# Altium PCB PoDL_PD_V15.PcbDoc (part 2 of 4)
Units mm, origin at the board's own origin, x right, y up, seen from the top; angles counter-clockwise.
Board outline 145 x 75 mm, 4 copper layers (Top Layer, Signal Layer 2, Signal Layer 3, Bottom Layer), stack 1.586 mm thick; 346 components, 228 nets, 1035 pads, 619 vias.
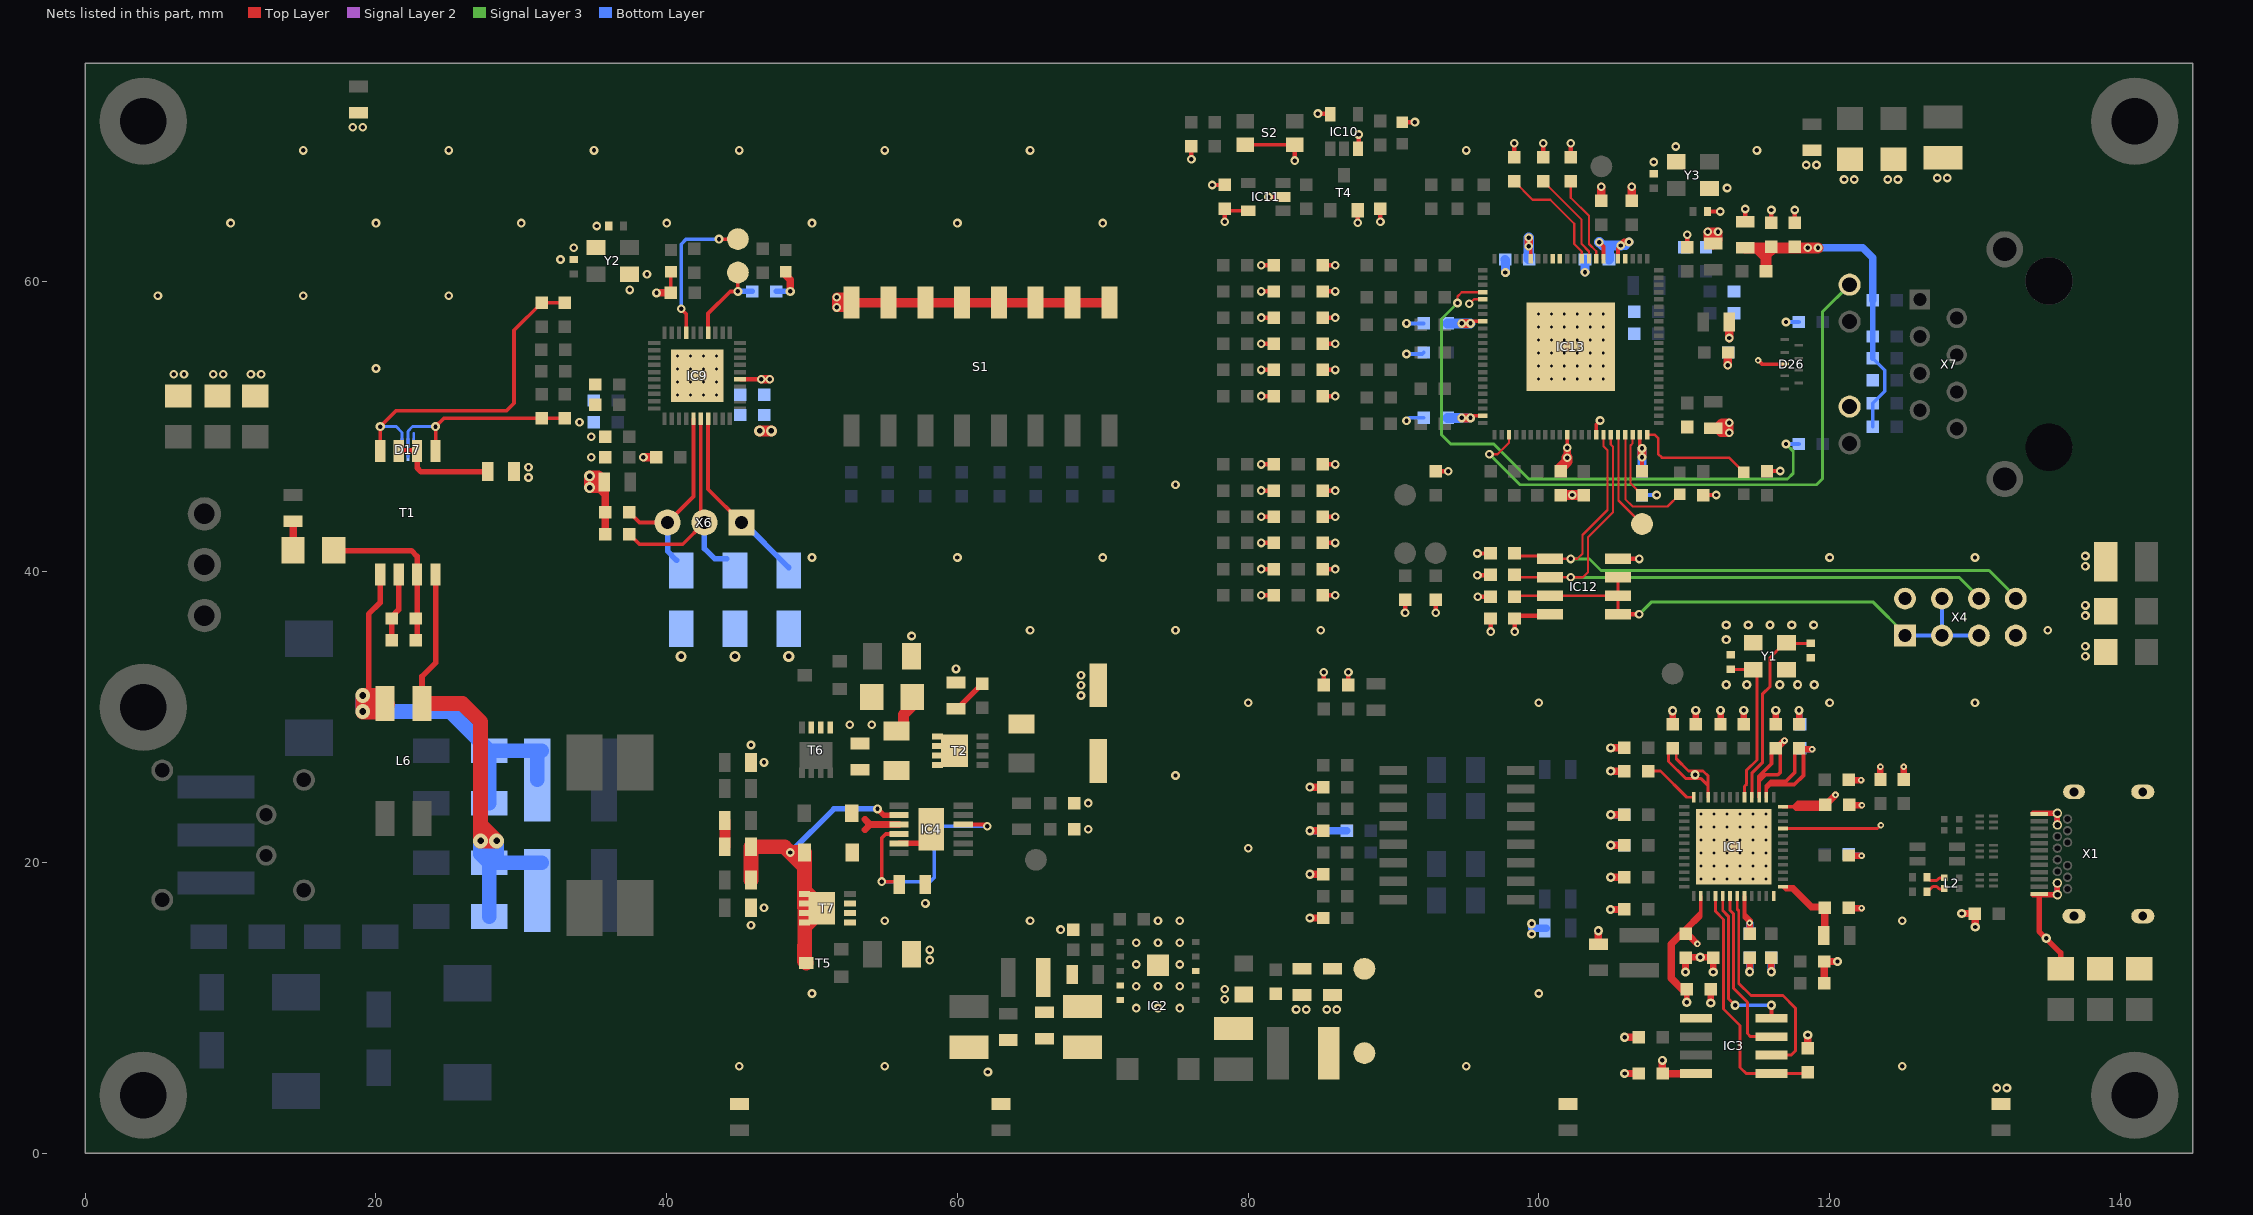
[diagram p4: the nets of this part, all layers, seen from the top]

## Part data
C1 C2: "CAP, CERM, 47nF, 100V, +/-10%, X7R, 0805", Dielectric=X7R, Manufacturer=Wurth, Supplier Part Number 1=710-885012207126, Tolerance_%=10
C3 C4 C5 C6 C10 C11 C12 C13 C14 C16 C21 C22 C23 C24 C40 C46 C47 C48 C49 C50 C51 C57 C59 C62 C63 C66 C67 C68 C69 C70 C71 C72 C75 C76 C77 C78 C79 C80 C81 C84: "CAP, CERM, 100nF, 25V, +/-10%, X7R, 0603", Dielectric=X7R, Manufacturer=Wurth, Supplier Part Number 1=710-885012206071, Tolerance_%=10
C7 C8: "CAP, CERM, 100nF, 25V, +/-20%, X5R, 0402", Dielectric=X5R, Manufacturer=Wurth, Supplier Part Number 1=710-885012105018, Tolerance_%=20
C9 C18 C20 C29 C60: "CAP, CERM, 1uF, 16V, +/-10%, X7R, 0603", Dielectric=X7R, Manufacturer=Wurth, Supplier Part Number 1=710-885012206052, Tolerance_%=10%
C15: "CAP, CERM, 22uF, 6.3V, +/-20%, X5R, 0805", Dielectric=X5R, Manufacturer=Wurth, Supplier Part Number 1=710-885012107005, Tolerance_%=20
C17: "CAP, CERM, 10uF, 6.3V, +/-20%, X5R, 0603", Dielectric=X5R, Manufacturer=Wurth, Supplier Part Number 1=710-885012106006, Tolerance_%=10
C19 C42 C104 C108: "CAP, CERM, 10nF, 100V, +/-10%, X7R, 1206", Dielectric=X7R, Manufacturer=Wurth, Supplier Part Number 1=710-885012208112, Tolerance_%=10
C25: "CAP, CERM, 10uF, 50V, +/-10%, X7R, 1210", Dielectric=X7R, Manufacturer=Wurth, Supplier Part Number 1=710-885012209073, Tolerance_%=10%
C26 C43: "CAP, CERM, 100nF, 50V, +/-10%, X7R, 0805", Dielectric=X7R, Manufacturer=Wurth, Supplier Part Number 1=710-885012207098, Tolerance_%=10
C27 C28: "CAP, CERM, 10uF, 10V, +/-10%, X7R, 0805", Dielectric=X7R, Manufacturer=Wurth, Supplier Part Number 1=710-885012207026, Tolerance_%=10
C30 C31 C55 C56 C82 C83: "CAP, CERM, 15pF, 50V, +/-5%, C0G, 0402", Dielectric=C0G, Manufacturer=Wurth, Supplier Part Number 1=732-7470-1-ND, Tolerance_%=5
C32: "CAP, CERM, 150nF, 100V, +/-10%, X7R, 1206", Dielectric=X7R, Manufacturer=Wurth, Supplier Part Number 1=710-885012208119, Tolerance_%=10
C33 C38 C96 C97: "CAP, CERM, 100nF, 100V, +/-10%, X7R, 0603", Dielectric=X7R, Manufacturer=Wurth, Supplier Part Number 1=710-885012206120, Tolerance_%=10
C34: "CAP, CERM, 22nF, 100V, +/-10%, X7R, 0805", Dielectric=X7R, Manufacturer=Wurth, Supplier Part Number 1=710-885012207124, Tolerance_%=10
C35: "CAP, ECAP, 47uF, 50V, +/-20%, 6.3mm x 7.7mm", Dielectric=-, Manufacturer=Wurth, Supplier Part Number 1=710-865080645012, Tolerance_%=20
C36: "CAP, CERM, 2.2uF, 6.3V, +/-10%, X7R, 0805", Dielectric=X7R, Manufacturer=Wurth, Supplier Part Number 1=710-885012207001, Tolerance_%=10
C37: "CAP, CERM, 100nF, 100V, +/-10%, X7R, 0805", Dielectric=X7R, Manufacturer=Wurth, Supplier Part Number 1=710-885012207128, Tolerance_%=10
C39 C44: "CAP, CERM, 10nF, 200V, +/-10%, X7R, 0805", Dielectric=X7R, Manufacturer=Wurth, Supplier Part Number 1=710-885342207005, Tolerance_%=10
C41: "CAP, CERM, 10nF, 1kV, +/-10%, X7R, 1206", Dielectric=X7R, Manufacturer=Wurth, Supplier Part Number 1=710-885342208021, Tolerance_%=10
C45 C52 C53 C54: "CAP, CERM, 47nF, 50V, +/-10%, X7R, 0603", Dielectric=X7R, Manufacturer=Wurth, Supplier Part Number 1=710-885012206093, Tolerance_%=10%
C58 C61 C64: "CAP, CERM, 10nF, 16V, +/-10%, X7R, 0603", Dielectric=X7R, Manufacturer=Wurth, Supplier Part Number 1=710-885012206040, Tolerance_%=10
C65: "CAP, CERM, 680nF, 16V, +/-10%, X7R, 0603", Dielectric=X7R, Manufacturer=Wurth, Supplier Part Number 1=710-885012206051, Tolerance_%=10
C73: "CAP, CERM, 1uF, 10V, +/-10%, X7R, 0603", Dielectric=X7R, Manufacturer=Wurth, Supplier Part Number 1=710-885012206026, Tolerance_%=10%
C74: "CAP, CERM, 470pF, 50V, +/-10%, X7R, 0603", Dielectric=X7R, Manufacturer=Wurth, Supplier Part Number 1=710-885012206081, Tolerance_%=10
C85 C86 C87 C88 C99 C100 C101 C102: "CAP, CERM, 10pF, 50V, +/-5%, C0G, 0603", Dielectric=C0G, Manufacturer=Wurth, Supplier Part Number 1=710-885012006051, Tolerance_%=5
C89 C98: "CAP, CERM, 22nF, 50V, +/-10%, X7R, 0603", Dielectric=X7R, Manufacturer=Wurth, Supplier Part Number 1=710-885012206091, Tolerance_%=10%
C90 C93: library part TBE_CAP_1210, "CAP, CERM, TBE, 1210"
C91 C92 C94 C95: library part TBE_CAP_1206, "CAP, CERM, TBE, 1206"
C103: "CAP, CERM, 1nF, 100V, +/-10%, X7R, 0805", Dielectric=X7R, Manufacturer=Wurth, Supplier Part Number 1=710-885012207116, Tolerance_%=10
C105 C106: "CAP, CERM, 4.7uF, 50V, +/-10%, X7R, 1210", Dielectric=X7R, Manufacturer=Wurth, Supplier Part Number 1=710-885012209048, Tolerance_%=10%
C107: "CAP, CERM, 1uF, 16V, +/-10%, X7R, 0805", Dielectric=X7R, Manufacturer=Wurth, Supplier Part Number 1=710-885012207051, Tolerance_%=10
C126: "CAP, CERM, 1nF, 50V, +/-5%, C0G, 0805", Dielectric=C0G, Manufacturer=Wurth, Supplier Part Number 1=710-885012007063, Tolerance_%=5
D1 D6: "DIODE, Schottky, 100V, 2A, SOD-123W", Manufacturer=Nexperia, Supplier Part Number 1=771-PMEG10020AELRX, Temperature="-55°C ~ 150°C", Voltage=100V
D2 D3 D4 D17: "DIODE, TVS Super Speed , 3.3V, DFN1210-6L", Manufacturer=Wurth, Supplier Part Number 1=710-824012823, Temperature="-55°C ~ 85°C", Voltage=3.3V
D5: "LED 570NM GREEN 0805 SMD", Manufacturer=Wurth, Supplier Part Number 1=710-150080VS75000
D7 D8 D9: "DIODE, TVS , 5V, 400W, Unidirection, SMA", Manufacturer=Wurth, Power=400W, Supplier Part Number 1=710-824500500, Temperature="-55°C ~ 150°C", Voltage=5V
D10: "Gas Discharge Tubes, 150V, 1pF, 5x7.5mm, SMD", Manufacturer=Bourns, Supplier Part Number 1=652-2038-15-SM-RPLF
D11 D12 D15 D16: "DIODE, Rectifiers, 100V, 1A, SMA", Manufacturer=Diodes, Supplier Part Number 1=621-S1B-F, Temperature="-65°C ~ 150°C", Voltage=100V
D13: "DIODE, TVS , 36V, 1.5kW, Bidirection, SMC", Manufacturer=Onsemi, Power=1500W, Supplier Part Number 1=512-SMCJ36CA, Temperature="-55°C ~ 150°C", Voltage=36V
D14 D18 D20 D21: "DIODE, Rectifiers, 200V, 1A, SMA", Manufacturer=Diodes, Supplier Part Number 1=621-S1D-F, Temperature="-65°C ~ 150°C", Voltage=200V
D19 D31: "DIODE, TVS , 36V, 1.5kW, Bidirection, SMC", Manufacturer=Wurth, Power=1500W, Supplier Part Number 1=710-824541361, Temperature="-55°C ~ 150°C", Voltage=36V
D23: "LED 587NM YELLOW 0603 SMD", Manufacturer="Lite-On Inc.", Supplier Part Number 1=859-LTST-C190KSKT
D24 D27 D28: "LED 572NM GREEN 0603 SMD", Manufacturer=Wurth, Supplier Part Number 1=710-150060VS75020
D25: "LED 645NM RED 0603 SMD", Manufacturer=Wurth, Supplier Part Number 1=710-150060SS75020
D26: "DIODE, TVS Super Speed , 5V, 8CH, 3.8x1.0mm", Manufacturer=Wurth, Supplier Part Number 1=710-824014885, Temperature="-55°C ~ 85°C", Voltage=5V/0.5pF
FB1 FB2 FB3 FB4 FB5 FB6 FB9 FB10 FB12: "Ferrite Bead 300R @ 100MHz / 0805 / 3.0A", Manufacturer=Wurth, Supplier Part Number 1=710-742792031
FB8: "Ferrite Bead 600R @ 100MHz / 0805 / 2.0A", Manufacturer=Wurth, Supplier Part Number 1=710-742792040
H1 H2 H3 H4 H5: Manufacturer=xxxx, Temperature="-55 to 150 °C"
IC1: "IC USB3.1 to 1G Ethernet Bridge, 3.3V, QFN-48", Manufacturer=Microchip, Supplier Part Number 1=579-LAN7800/Y9X
IC2: "IC REG BUCK, ADJ, 3A, LGA-16EP", Manufacturer=Wurth, Supplier Part Number 1=710-171033801
IC3: "IC EEPROM, SPI, 4kb, 16MHz, 1.8-5.5V, SO-8", Manufacturer=Microchip, Supplier Part Number 1=579-93AA66C-I/SN
IC4: "IC SPoE PD, 10Base-T1L, 2.3-60V, MSOP-12", Manufacturer="Analog Devices", Supplier Part Number 1=584-LTC9111RMSE#PBF
IC9: "IC Ethernet 10BASE-T1L PHY, 3.3V, LFCSP-40", Manufacturer=Microchip, Supplier Part Number 1=505-ADIN1100CCPZ-R7CT-ND
IC10: library part 74LVC1G14GV,125_2, "IC SCHMITT INVERTER, 1.65-5.5V, 1CH, SOT-753", Manufacturer=Nexperia, Supplier Part Number 1=771-74LVC1G14GV
IC11: "IC Supervisory, 0.75-3.3V, SOT-23-5", Manufacturer=TI, Supplier Part Number 1=595-TPS3125L30DBVR, Threshold Voltage=2.64V
IC12: "IC EEPROM, I2C, 512kb, 1MHz, 1.7-5.5V, SO-8", Manufacturer=Microchip, Supplier Part Number 1=579-24FC512-I/SN
IC13: "IC ETHERNET SWITCH 3PORT, VQFN-88", Manufacturer=Microchip, Supplier Part Number 1=LAN9355I/ML-ND
L1: "Coupled Inductor 2x470uH / 12.5x12.5mm /0.7A", Manufacturer=Wurth, PartNumber=744870471
L2 L3: "Common Mode Chokes 60R @ 100MHz / 1x1.2mm / 600mA", Manufacturer=Wurth, Supplier Part Number 1=710-7442335600
L4: "Inductor 3.3uH / 3015 / 1.5A", Inductance=3.3uH, Manufacturer=Wurth, Supplier Part Number 1=710-74404032033
L5: "Common Mode Chokes 90R @ 100MHz / 1206 / 370mA", Manufacturer=Wurth, Supplier Part Number 1=710-744232090
L6: "Common Mode Chokes 2x250uH / 9.2x6mm / 1200mA", Manufacturer=Wurth, Supplier Part Number 1=710-744224
L8 L10: "Inductor 22uH / 6045 / 2.1A", Inductance=22uH, Manufacturer=Wurth, Supplier Part Number 1=710-74404064220
L11: "Inductor 22uH / 3015 / 0.6A", Inductance=22uH, Manufacturer=Wurth, Supplier Part Number 1=710-74404032220
L12: "Inductor 4.7uH / 4018 / 1.7A", Inductance=4.7uH, Manufacturer=Wurth, Supplier Part Number 1=710-74404042047
R2 R65 R68: "RES, 5.1kohm, 1%, 0.1W, 0603", Manufacturer=Yageo, Power_W=0.1, Supplier Part Number 1=603-RC0603FR-075K1L, Tolerance_%=1%
R3 R27: "RES, 100 ohm, 1%, 0.125W, 0805", Manufacturer=Wurth, Power_W=0.125, Supplier Part Number 1=710-560112120020, Tolerance_%=1%
R4 R90 R91 R92 R93: "RES, 330 ohm, 1%, 0.1W, 0603", Manufacturer=Wurth, Power_W=0.1, Supplier Part Number 1=710-560112116020, Tolerance_%=1%
R5 R6 R10 R12 R17 R18 R61 R63 R66 R67 R73 R82 R84 R88 R89 R100 R101 R102 R103 R104 R105 R138 R139 R140 R141 R142 R143 R151 R152: "RES, 10kohm, 1%, 0.1W, 0603", Manufacturer=Wurth, Power_W=0.1, Supplier Part Number 1=710-560112116005, Tolerance_%=1%
R7 R74 R85 R86: "RES, 2kohm, 1%, 0.1W, 0603", Manufacturer=Wurth, Power_W=0.1, Supplier Part Number 1=710-560112116091, Tolerance_%=1%
R8: "RES, 10kohm, 1%, 0.1W, 0603", Manufacturer=Yageo, Power_W=0.1, Supplier Part Number 1=603-RC0603FR-0710KL, Tolerance_%=1%
R9: "RES, 40.2 ohm, 1%, 0.25W, 1206", Manufacturer=Yageo, Power_W=0.25, Supplier Part Number 1=603-RC1206FR-0740R2L, Tolerance_%=-
R11: "RES, 12kohm, 1%, 0.1W, 0603", Manufacturer=Wurth, Power_W=0.1, Supplier Part Number 1=710-560112116040, Tolerance_%=1%
R13 R14 R15: "RES, 3.3 ohm, 1%, 0.25W, 1206", Manufacturer=Yageo, Power_W=0.25, Supplier Part Number 1=603-RC1206FR-073R3L, Tolerance_%=1%
R16 R19 R20 R21 R22 R23: "RES, 0 ohm, -%, 0.125W, 0805", Manufacturer=Yageo, Power_W=0.125, Supplier Part Number 1=311-0.0ARCT-ND, Tolerance_%=-%
R24: "RES, 402kohm, 1%, 0.1W, 0603", Manufacturer=Yageo, Power_W=0.1, Supplier Part Number 1=603-RC0603FR-07402KL, Tolerance_%=1%
R25: "RES, 5.6kohm, 1%, 0.1W, 0603", Manufacturer=Wurth, Power_W=0.1, Supplier Part Number 1=710-560112116017, Tolerance_%=1%
R26: "RES, 137kohm, 1%, 0.1W, 0603", Manufacturer=Yageo, Power_W=0.1, Supplier Part Number 1=603-RC0603FR-07137KL, Tolerance_%=1%
R52 R53 R54 R55 R56 R57 R58 R59 R60 R62 R72 R87: "RES, 4.7kohm, 1%, 0.1W, 0603", Manufacturer=Wurth, Power_W=0.1, Supplier Part Number 1=710-560112116006, Tolerance_%=1%
R64 R69 R77 R78 R79 R80 R154 R155 R156 R157: "RES, 49.9 ohm, 1%, 0.1W, 0603", Manufacturer=Wurth, Power_W=0.1, Supplier Part Number 1=710-560112116133, Tolerance_%=1%
R70 R71 R150: "RES, 1.5kohm, 1%, 0.1W, 0603", Manufacturer=Wurth, Power_W=0.1, Supplier Part Number 1=710-560112116038, Tolerance_%=1%
R75: "RES, 100 ohm, 1%, 0.1W, 0603", Manufacturer=Wurth, Power_W=0.1, Supplier Part Number 1=710-560112116009, Tolerance_%=1%
R76: "RES, 1kohm, 1%, 0.1W, 0603", Manufacturer=Wurth, Power_W=0.1, Supplier Part Number 1=710-560112116014, Tolerance_%=1%
R81 R94 R95 R96 R97 R98 R99 R106 R107 R108 R109 R110 R111 R132 R133 R134 R135 R136 R137 R144 R145 R146 R147 R148 R149 R153 R164: "RES, 0 ohm, 1%, 0.1W, 0603", Manufacturer=Yageo, Power_W=0.1, Supplier Part Number 1=603-RC0603FR-070RL, Tolerance_%=1%
R83: "RES, 12.1kohm, 1%, 0.1W, 0603", Manufacturer=Yageo, Power_W=0.1, Supplier Part Number 1=603-RC0603FR-0712K1L, Tolerance_%=1%
R112 R113 R114 R115 R116 R117 R118 R119 R120 R121 R122 R123 R124 R125 R126 R127 R128 R129 R130 R131: "RES, 33 ohm, 1%, 0.1W, 0603", Manufacturer=Wurth, Power_W=0.1, Supplier Part Number 1=710-560112116034, Tolerance_%=1%
R158 R159: "RES, 75 ohm, 1%, 0.125W, 0805", Manufacturer=Yageo, Power_W=0.125, Supplier Part Number 1=603-RC0805FR-0775RL, Tolerance_%=1%
R160 R161 R162 R163: "RES, 0 ohm, -%, 0.25W, 1206", Manufacturer=Vishay, Power_W=0.25, Supplier Part Number 1=541-0.0ECT-ND, Tolerance_%=-
S1: "DIP SWITCH, SPST, 0.025A, 24V", Manufacturer=Wurth, Supplier Part Number 1=710-418121270808
S2: "SWITCH TACTILE, SPST-NO, 350gf, 0.05A, 12V", Manufacturer=Wurth, Supplier Part Number 1=710-434153017835
T1: "Trans, PoDL, 2.2mH, SMT", Manufacturer=Wurth
T2: "MOSFET, N-CH, 100V, 18A, LFPAK33", Manufacturer=Nexperia, Supplier Part Number 1=771-PSMN075-100MSEX
T3 T5: "MOSFET, N-CH, 100V, 0.17A, SOT-23", Manufacturer=Onsemi, Supplier Part Number 1=863-BSS123LT1G
T4: "MOSFET, N-CH, 50V, 0.2A, SOT-23", Manufacturer=Onsemi, Supplier Part Number 1=863-BSS138LT1G
T6 T7: "MOSFET, N-CH, 100V, 11.5A, LFPAK33", Manufacturer=Nexperia, Supplier Part Number 1=771-BUK9M120-100EX
TP1 TP2 TP3 TP4 TP5 TP6 TP7 TP8 TP9 TP10 TP11: library part "TP / 1.5mm", "Test Point, SMT, Miniature"
VAR1 VAR2: "Varistor, 85Vdc, 60Vac, 160pF, 1206", Manufacturer=Wurth, Supplier Part Number 1=710-82551600
X1: "CON, USB, Type C, Female, 24P, Hor, SMT", Manufacturer=Wurth, Supplier Part Number 1=710-632723300011
X2: "CON, SPE, 2P, Shield, 4A, R/A, INS", Manufacturer=HARTING, Supplier Part Number 1=617-09452812810
X3: "CON, Terminal Block, Plug-in, 3P, P3.5mm, 10A, R/A, INS", Manufacturer=Wurth, Supplier Part Number 1=710-691322110003
X4: "CON, Header, Male, 2x4P, P2.54mm, Straight, INS", Manufacturer=Wurth, Supplier Part Number 1=710-61300821121
X6: "CON, Header, Male, 3P, P2.54mm, Straight, INS", Manufacturer=Wurth, Supplier Part Number 1=710-61300311121
X7: "CON, Ethernet, Int Magnetics, 8P+LED, 1x1 Tab-UP, INS", Manufacturer=Wurth, Supplier Part Number 1=710-74990112116A
X8: "Trans, Ethernet, 10/100 Base-T, SMT", Manufacturer=Wurth, Supplier Part Number 1=710-7490100110A
Y1 Y2 Y3: "Crystal / 25MHz / 18pF / 30ppm", Load Capacitance=18pF, Manufacturer=Wurth, Package=3.2x2.5x0.8mm, Supplier Part Number 1=710-830055299

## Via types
v1: diameter 0.6, hole 0.3, Top Layer to Bottom Layer, tented both sides, 350 vias
v2: diameter 0.45, hole 0.2, Top Layer to Bottom Layer, tented both sides, 137 vias
v3: diameter 0.635, hole 0.3, Top Layer to Bottom Layer, tented both sides, 77 vias
v4: diameter 1.016, hole 0.508, Top Layer to Bottom Layer, 40 vias
v5: diameter 1.016, hole 0.457, Top Layer to Bottom Layer, tented both sides, 8 vias
v6: diameter 0.762, hole 0.381, Top Layer to Bottom Layer, tented both sides, 7 vias

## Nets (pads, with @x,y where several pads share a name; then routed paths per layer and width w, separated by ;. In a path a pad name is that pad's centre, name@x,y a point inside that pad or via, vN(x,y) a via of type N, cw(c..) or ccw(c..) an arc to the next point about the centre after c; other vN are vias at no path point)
+3V3: C16.1 C17.2 C18.1 C21.1 C22.1 C23.1 C24.1 C27.1 C28.1 C40.1 C50.1 C51.1 C61.1 C62.1 C66.2 C67.1 C68.1 C69.1 C70.1 C71.1 C72.1 C84.2 D23.2 D24.2 FB1.1 FB2.1 FB4.1 FB6.1 IC1.14 IC1.20 IC1.36 IC1.38 IC1.39 IC1.46 IC3.8 IC9.35 IC10.5 IC11.5 IC12.8 IC13.5 IC13.7 IC13.17 IC13.30 IC13.43 IC13.55 IC13.65 L12.2 R4.1 R5.1 R6.1 R8.2 R60.2 R61.2 R70.1 R71.1 R72.1 R73.2 R85.1 R86.1 R89.1 R90.2 R92.1 R93.1 R94.2 R95.2 R96.2 R97.2 R98.2 R99.2 R132.2 R133.2 R134.2 R135.2 R136.2 R137.2 R150.2 R152.1 S1.9 S1.10 S1.11 S1.12 S1.13 S1.14 S1.15 S1.16 TP11.1 X4.2 | length 153.6
  Top Layer w0.2: C18.1@108.92,27.55 108.92,26.97 110.085,25.805 111.133,25.805 111.65,25.288 ; C18.1@109.45,27.48 109.45,27.155 110.3,26.305 111.3,26.305 111.65,25.955 111.65,25.288 ; IC1.46@111.65,24.5 111.65,25.288 ; C24.1@116,27.48 C24.1@116.3,27.78
  Top Layer w0.25: R61.2@40.275,59.2 40.275,60.625 D23.2@40.3,60.65 ; C16.1@109.893,15.348 111.15,16.605 ; C16.1@110.25,15.188 110.25,15.405 111.15,16.305 111.15,16.605 ; IC1.14@111.15,17.7 111.15,16.605 ; R93.1@111.3,45.275 R93.1@111.325,45.3 ; IC1.20@114.15,17.7 114.15,16.481 ; C21.1@114.4,15.34 114.4,15.957 114.15,16.207 114.15,16.481 ; C21.1@114.5,15.081 114.6,15.181 114.6,16.031 114.15,16.481 ; IC1.36@116.8,23.85 117.525,23.85 ; 117.805,24.15 C22.1@119.475,24.15 ; C22.1@119.425,24.08 117.755,24.08 117.525,23.85 ; C22.1@119.499,23.68 117.695,23.68 117.525,23.85 ; C22.1@119.499,23.78 C22.1@119.569,23.85 ; C22.1@119.669,23.85 C22.1@119.569,23.85 ; C22.1@119.7,23.98 C22.1@119.569,23.85 ; 117.525,23.85 C22.1@119.569,23.85
  Top Layer w0.254: C66.2@78.4,64.975 78.524,64.85 IC11.5@80,64.85 ; v1@95.45,50.75 IC13.43@96.15,50.75 ; v1@95.473,57.25 IC13.30@96.15,57.25 ; IC13.17@99.45,61.55 v1@99.45,62.227 ; v1(101.95,48.539) IC13.55@101.95,49.45 ; v1(104.15,62.688) 104.45,62.388 IC13.7@104.45,61.55 ; IC13.5@105.45,61.55 105.45,62.274 v1(105.635,62.459) ; v1@106.95,48.1 IC13.65@106.95,49.45 ; R89.1@107.1,46.925 v1(107.1,47.9) ; FB6.1@111.75,49.9 FB6.1@112,49.9 ; IC1.39@115.15,24.5 115.15,25.605 ; IC1.38@115.65,24.5 115.65,25.105 ; C24.1@116,27.48 116,26.805 115.15,25.955 115.15,25.605 ; C24.1@116.3,27.78 116.6,27.48 116.6,26.205 116.445,26.05 115.595,26.05 115.15,25.605 ; 115.65,25.105 115.65,25.3 115.955,25.605 117,25.605 117.6,26.205 117.6,27.48 117.9,27.78 118.2,27.48 118.2,26.005 117.576,25.381 115.925,25.381 115.65,25.105
  Top Layer w0.3: v1(76.1,68.4) R73.2@76.1,69.274 ; v1(78.4,64.1) C66.2@78.4,64.975 ; v1(84.8,71.535) IC10.5@85.674,71.535 ; R136.2@85.126,38.4 v1(86,38.4) ; R137.2@85.126,40.2 v1(86,40.2) ; R135.2@85.125,42 v1(86,42) ; R134.2@85.125,43.8 v1(86,43.8) ; R133.2@85.126,45.6 v1(86,45.6) ; R132.2@85.126,47.4 v1(86,47.4) ; R98.2@85.125,52.1 v1(86,52.1) ; R99.2@85.125,53.9 v1(86,53.9) ; R97.2@85.125,55.7 v1(86,55.7) ; R96.2@85.125,57.5 v1(86,57.5) ; R95.2@85.125,59.3 v1(86,59.3) ; R94.2@85.125,61.1 v1(86,61.1) ; v1(89.1,64.1) R72.1@89.1,64.975 ; v1(92.9,37.2) R150.2@92.9,38.075 ; R152.1@92.9,46.925 v1(93.774,46.925) ; v1(95.775,39.775) R85.1@96.649,39.775 ; v1(95.775,41.275) R86.1@96.649,41.275 ; v1(98.351,35.9) C84.2@98.351,36.775 ; C84.2@98.43,37 IC12.8@100.8,37 ; R93.1@111.325,45.3 v1(112.2,45.3) ; R92.1@115.725,46.951 v1(116.6,46.951)
  Top Layer w0.305: IC9.35@45.05,53.25 v1(46.5,53.25)
  Top Layer w0.4: v3(110.174,10.395) C17.2@110.174,11.3
  Top Layer w0.45: C16.1@110.322,14.997 v2(110.905,14.415) ; C24.1@116.318,27.823 v2(116.9,28.405) ; C23.1@117.9,27.78 117.926,27.805 v2(118.8,27.805) ; C22.1@119.825,24.08 v2(120.407,24.662) ; R6.1@123.5,25.726 v2(123.5,26.6)
  Top Layer w0.5: C17.2@109.905,11.251 109.1,12.055 109.1,14.407 109.754,15.061 C16.1@110.09,15.061
  Top Layer w0.508: FB1.1@35.3,45.8 35.3,45.775 35.775,45.3 ; FB1.1@35.7,46.2 35.775,46.125 35.775,45.3 ; R71.1@35.775,42.6 R70.1@35.775,44.1 35.775,45.3 ; v3(39.3,59.2) R61.2@40.275,59.2 ; D24.2@48.2,60.65 48.2,60.4 48.5,60.1 v3(48.5,59.3) ; v1(101.95,47.861) v1(101.95,48.539) ; v1(105.635,62.459) 105.876,62.7 v1(106.2,62.7) ; v3(108.5,6.4) 108.5,5.5 108.526,5.475 110.78,5.475 IC3.8@110.8,5.495 ; R8.2@119.626,11.7 R5.1@119.626,13.2 v3(120.55,13.2)
  Top Layer w0.6: v1(46.5,53.25) v1(47.1,53.25) ; v1(94.7,50.6) v1(95.3,50.6) ; v1(94.7,57.1) v1(95.3,57.1) ; v1(99.3,62.4) v1(99.3,63) ; v1(107.1,47.9) v1(107.1,48.5) ; v1(113.1,56.097) FB2.1@113.1,57.2 ; 111.975,63.4 112,63.375 FB4.1@112,62.5 ; 111.975,63.4 v1(111.625,63.4) 111.625,62.875 FB4.1@112,62.5 ; 111.975,63.4 v1(112.325,63.4) 112.325,62.825 FB4.1@112,62.5 ; FB6.1@112.2,49.9 113.075,49.9 113.1,49.925 ; FB6.1@112.2,49.9 112.575,50.275 v1(113.1,50.275) 113.1,49.925 ; FB6.1@112.2,49.9 112.525,49.575 v1(113.1,49.575) 113.1,49.925
  Top Layer w0.635: S1.9@70.47,58.525 S1.10@67.93,58.525 S1.11@65.39,58.525 S1.12@62.87,58.525 S1.13@60.33,58.525 S1.14@57.79,58.525 S1.15@55.27,58.525 S1.16@52.73,58.525 ; 51.7,58.55 v1(51.7,58.9) 52.355,58.9 S1.16@52.73,58.525 ; 51.7,58.55 v1(51.7,58.2) 52.405,58.2 S1.16@52.73,58.525 ; 51.7,58.55 51.725,58.525 S1.16@52.73,58.525
  Top Layer w0.762: v6(46.4,49.7) v6(47.2,49.7) ; C71.1@101.5,46.9 C71.1@101.5,46.925 101.5,47.146 101.95,47.596 v1(101.95,47.861) ; 34.7,46.2 v6(34.7,46.6) 35.3,46.6 FB1.1@35.7,46.2 ; 34.7,46.2 v6(34.7,45.8) 35.3,45.8 FB1.1@35.7,46.2 ; 34.7,46.2 FB1.1@35.7,46.2
  Bottom Layer w0.3: v1(117,57.2) R90.2@117.874,57.2
  Bottom Layer w0.381: R60.2@47.526,59.3 v3(48.5,59.3)
  Bottom Layer w0.45: C51.1@118.026,27.805 v2(118.8,27.805)
  Bottom Layer w0.508: C50.1@114.5,15.08 v2(114.5,15.855)
  Bottom Layer w0.6: v1(94.7,50.6) v1(95.3,50.6) ; C68.1@99.3,61.526 C68.1@99.325,61.5 ; v1(105.635,62.459) 105.959,62.459 v1(106.2,62.7) ; C72.1@107.1,47.026 v1(107.1,47.9) v1(107.1,48.5)
  Bottom Layer w0.7: C70.1@93.725,50.6 v1(94.7,50.6) ; C69.1@93.725,57.1 v1(94.7,57.1) v1(95.3,57.1) ; C68.1@99.3,61.526 v1(99.3,62.4) v1(99.3,63) ; v1(104.15,62.688) 104.379,62.459 104.8,62.459 ; C67.1@104.825,61.5 104.825,62.434 104.8,62.459 ; v1(105.635,62.459) 104.8,62.459
  other v1: 83.3,9.9 84,9.9 85.4,9.9 86.1,9.9
  other v3: 110.75,26.045
A0: IC12.1 IC12.2 IC12.3 IC12.7 R87.1 X4.1 X4.3 X4.4 X4.5 | length 38.3
  Top Layer w0.203: R87.1@98.326,38.3 98.39,38.365 IC12.7@100.76,38.365 IC12.2@105.44,38.365 ; IC12.1@105.44,37.095 IC12.2@105.44,38.365 ; IC12.3@105.44,39.635 IC12.2@105.44,38.365
  Top Layer w0.3: IC12.1@105.44,37.095 v1(106.895,37.095)
  Signal Layer 3 w0.203: v1@106.9,37.09 107.76,37.95 122.97,37.95 X4.1@125.19,35.73
  Bottom Layer w0.254: X4.1@125.19,35.63 X4.3@127.73,35.63 ; X4.4@127.73,38.17 X4.3@127.73,35.63 ; X4.5@130.27,35.63 X4.3@127.73,35.63
ATEST/FXLOSEN: IC13.8 R84.2 | length 6
  Top Layer w0.152: R84.2@102.2,66.874 102.2,65.75 103.451,64.499 103.451,62.561 103.95,62.062 IC13.8@103.95,61.55
CLK25_REF: IC9.7 TP3.1 | length 10.3
  Top Layer w0.254: v1(41,58.1) 41.35,57.75 IC9.7@41.35,56.45 ; v1(43.6,62.9) TP3.1@44.9,62.9
  Bottom Layer w0.254: v1(41,58.1) 41,62.55 41.35,62.9 v1(43.6,62.9)
D_N: D17.1 D17.6 R64.1 R65.1 T1.4 | length 24.1
  Top Layer w0.254: T1.4@20.295,48.35 v3@20.295,49.979 ; v3(20.3,50) 21.4,51.1 29,51.1 29.5,51.6 29.5,56.626 R64.1@31.4,58.526 R65.1@33,58.526
  Bottom Layer w0.203: v3(20.3,50) 21.4,50 21.8,49.6 D17.6@21.8,47.925
D_P: D17.2 D17.5 R68.1 R69.1 T1.1 | length 14.6
  Top Layer w0.254: v3(24.1,50) 24.675,50.575 R68.1@33,50.575 ; T1.1@24.105,48.32 v3@24.105,49.955
  Bottom Layer w0.203: D17.5@22.2,47.925 22.2,49.679 22.52,50 v3(24.1,50)
Data_N: D20.1 D21.2 L6.1 L10.2 T1.5 | length 35.1
  Top Layer w0.381: v5@19.495,31.6 19.495,37.095 20.295,37.895 T1.5@20.295,39.82 ; L6.1@20.65,31.15 L6.1@20.65,31.45
  Top Layer w1.016: v5@19.1,30.355 L6.1@20.355,30.355 ; v5@19.1,30.45 v5(19.1,31.5) L6.1@20.1,31.5 ; 19.55,30.9 L6.1@20.8,30.9
  Bottom Layer w1.016: D21.2@27.8,24.1 D20.1@27.8,27.7 ; L10.2@31.1,25.7 L10.2@31.1,27.7 ; L10.2@31.4,27.7 L10.2@31.1,27.7 ; 20.2,30.4 25.1,30.4 D20.1@27.8,27.7 ; 20.2,30.4 v5(19.1,30.4) v5(19.1,31.5) 20.2,30.4 ; D20.1@27.8,27.7 L10.2@31.1,27.7
Data_P: D14.1 D18.2 L6.2 L8.2 T1.8 | length 38
  Top Layer w0.381: L6.2@23.17,31.05 23.17,32.82 24.1,33.75 T1.8@24.1,39.82
  Top Layer w1.016: L6.2@23.17,30.95 25.95,30.95 27.2,29.7 27.2,22.6 ; 27.2,22.6 v5(28.3,21.5) v5(27.2,21.5) 27.2,22.6
  Bottom Layer w1.016: D18.2@27.8,16.3 D14.1@27.8,19.9 ; L8.2@31.4,20 D14.1@27.8,20 ; D14.1@27.8,20 27.8,21 v5(28.3,21.5) ; D14.1@27.8,20 27.2,20.6 v5(27.2,21.5) v5(28.3,21.5) ; D14.1@27.8,20 28.3,20.5 v5(28.3,21.5)
EECLK: IC1.19 IC3.2 | length 15.4
  Top Layer w0.203: IC1.19@113.65,17.7 113.65,16.796 113.754,16.693 113.754,11.697 114.589,10.861 116.796,10.861 117.646,10.011 117.646,7.046 117.365,6.765 IC3.2@116,6.765
EECS: IC1.16 IC3.1 R18.1 | length 17.3
  Top Layer w0.203: IC1.16@112.15,17.7 112.15,16.655 112.706,16.099 112.706,9.938 113.844,8.8 113.844,5.921 114.269,5.495 IC3.1@116,5.495 118.42,5.495 R18.1@118.5,5.574
EEDI: IC1.17 IC3.4 | length 11.2
  Top Layer w0.203: IC1.17@112.65,17.7 112.65,16.705 113.037,16.318 113.037,10.663 v3(113.5,10.2)
  Top Layer w0.254: IC3.4@116,9.305 v3(116,10.2)
  Bottom Layer w0.254: v3(113.5,10.2) v3(116,10.2)
EEDO: IC1.18 IC3.3 | length 11.7
  Top Layer w0.203: IC1.18@113.15,17.7 113.15,16.725 113.406,16.469 113.406,11.343 114.354,10.395 114.354,8.246 114.565,8.035 IC3.3@116,8.035
FXSDA/FXLOSA: IC13.9 R82.1 | length 6.6
  Top Layer w0.152: R82.1@100.3,66.874 102.943,64.231 102.943,62.561 103.45,62.054 IC13.9@103.45,61.55
FXSDB/FXLOSB: IC13.10 R88.1 | length 8
  Top Layer w0.152: R88.1@98.3,66.874 99.566,65.609 100.791,65.609 102.435,63.965 102.435,62.561 102.95,62.046 IC13.10@102.95,61.55
GND: C1.2 C3.2 C4.2 C5.2 C6.2 C9.2 C10.2 C11.2 C12.2 C13.2 C14.2 C15.1 C16.2 C17.1 C18.2 C19.1 C20.2 C21.2 C22.2 C23.2 C24.2 C25.2 C26.2 C27.2 C28.2 C29.2 C30.1 C31.1 C32.2 C34.2 C35.2 C36.2 C37.2 C39.2 C40.2 C42.2 C43.2 C44.2 C45.2 C46.2 C47.2 C48.2 C49.2 C50.2 C51.2 C52.2 C53.2 C54.2 C55.1 C56.1 C57.2 C58.2 C59.2 C60.2 C61.2 C62.2 C63.2 C64.2 C65.2 C66.1 C67.2 C68.2 C69.2 C70.2 C71.2 C72.2 C73.1 C74.2 C75.2 C76.2 C77.2 C78.2 C79.2 C80.2 C81.2 C82.1 C83.1 C84.1 C85.2 C86.2 C87.2 C88.2 C89.2 C90.2 C91.2 C92.2 C93.2 C94.2 C95.2 C96.2 C97.2 C98.2 C99.2 C100.2 C101.2 C102.2 C103.2 C104.2 C105.2 C106.2 C107.2 C108.1 C126.2 D5.1 D7.1 D8.1 D9.1 D17.3 D25.1 D26.3 IC1.49 IC2.10 IC2.13 IC3.5 IC4.5 IC4.EPAD IC9.41 IC10.3 IC11.2 IC12.4 IC13.4 IC13.59 IC13.89 R2.2 R7.2 R11.2 R12.2 R14.2 R15.2 R16.1 R17.2 R18.2 R19.1 R20.1 R21.1 R22.1 R23.1 R26.2 R82.2 R83.2 R84.1 R87.2 R88.2 R106.1 R107.1 R108.1 R109.1 R110.1 R111.1 R144.1 R145.1 R146.1 R147.1 R148.1 R149.1 R151.1 S2.1 S2.3 T4.2 T6.1 T6.2 T6.3 T7.1 T7.2 T7.3 TP10.1 VAR1.1 VAR2.2 X1.A1 X1.A12 X1.B1 X1.B12 X1.SH1 X1.SH2 X1.SH3 X1.SH4 X4.7 X7.P11 Y1.2 Y1.4 Y2.2 Y2.4 Y3.2 Y3.4 | length 104.2
  Top Layer w0.254: S2.3@79.45,69.4 S2.1@83.55,69.4 ; IC13.59@103.95,49.45 103.95,50.16 v1(104.213,50.423) ; v2(115.087,54.559) 115.347,54.3 D26.3@116.925,54.3
  Top Layer w0.3: v1(77.525,66.626) C66.1@78.4,66.626 ; v1(80.9,38.4) R148.1@81.774,38.4 ; v1(80.9,40.2) R149.1@81.774,40.2 ; v1(80.9,42) R147.1@81.774,42 ; v1(80.9,43.8) R146.1@81.774,43.8 ; v1(80.9,45.6) R145.1@81.774,45.6 ; v1(80.9,47.4) R144.1@81.774,47.4 ; v1(80.9,52.1) R110.1@81.774,52.1 ; v1(80.9,53.9) R111.1@81.774,53.9 ; v1(80.9,55.7) R109.1@81.774,55.7 ; v1(80.9,57.5) R108.1@81.774,57.5 ; v1(80.9,59.3) R107.1@81.774,59.3 ; v1(80.9,61.1) R106.1@81.774,61.1 ; v1(81.4,65.8) IC11.2@82.4,65.8 ; v1(83.2,68.3) S2.1@83.2,69.3 ; S2.1@83.55,69.4 S2.1@83.6,69.35 ; C53.2@85.2,32.226 v1(85.2,33.1) ; C54.2@86.9,32.226 v1(86.9,33.1) ; v1(87.55,64.026) T4.2@87.55,64.9 ; IC10.3@87.55,69.1 87.6,69.15 v1(87.6,70.1) ; D25.1@90.6,70.95 v1(91.474,70.95) ; v1(90.8,37.2) R151.1@90.8,38.075 ; v1(95.8,38.3) R87.2@96.675,38.3 ; v1(96.7,35.9) C84.1@96.7,36.775 ; R88.2@98.3,68.525 v1(98.3,69.5) ; R82.2@100.3,68.525 v1(100.3,69.5) ; R84.1@102.2,68.525 v1(102.2,69.5) ; IC12.4@105.44,40.905 105.445,40.9 v1(106.9,40.9) ; C78.2@110.2,62.326 v1(110.2,63.2) ; C82.1@111.6,64.8 v1(112.474,64.8) ; C126.2@114.2,64.1 v1(114.2,64.974) ; C45.2@116,64.026 v1(116,64.9) ; C52.2@117.6,64.026 v1(117.6,64.9)
  Top Layer w0.381: IC4.5@55.984,21.325 57.825,21.325 58.2,21.7 IC4.EPAD@58.2,22.3 ; X1.A1@134,17.8 X1.A1@134.42,17.8 ; X1.A12@134,23.4 X1.B1@135.67,23.4 X1.B1@135.67,22.6 ; X1.B12@135.67,18.6 X1.B12@135.67,17.8 X1.A1@134.42,17.8 ; C108.1@135.9,12.7 135.9,13.8 v3(134.9,14.8) 134.42,15.28 X1.A1@134.42,17.8
  Top Layer w0.45: C18.2@109.2,29.5 C18.2@109.2,29.526 v3(109.2,30.453) ; v3(110.09,12.482) C16.2@110.09,13.435 ; C16.2@110.154,13.498 v3(111.106,13.498) 111.932,13.498 111.995,13.435 v3(111.995,12.482) ; C20.2@110.8,29.526 v3(110.8,30.478) ; v3(111.825,10.348) C17.1@111.825,11.3 ; C6.2@112.5,29.526 v3(112.5,30.478) ; C5.2@114.1,29.526 v3(114.1,30.478) ; v3(114.5,12.502) C21.2@114.5,13.455 ; v3(116,12.502) C3.2@116,13.455 ; C24.2@116.3,29.526 v3(116.3,30.478) ; C23.2@117.9,29.526 v3(117.9,30.478) ; R11.2@121.3,25.68 v2(122.174,25.68) ; C9.2@121.326,16.88 v2(122.2,16.88) ; C4.2@121.326,20.48 v2(122.2,20.48) ; C22.2@121.351,23.955 v2(122.225,23.955) ; R12.2@125.1,25.726 v2(125.1,26.6)
  Top Layer w0.508: v3(84.25,16.2) C99.2@85.175,16.2 ; v3(84.25,19.2) C100.2@85.175,19.2 ; v3(84.25,22.2) C101.2@85.175,22.2 ; v3(84.25,25.2) C102.2@85.175,25.2 ; C15.1@104.096,14.398 v3(104.096,15.323) ; v3(104.925,16.78) C13.2@105.849,16.78 ; v3(104.95,19) C12.2@105.875,19 ; v3(104.95,21.2) C11.2@105.875,21.2 ; v3(104.95,23.3) C10.2@105.875,23.3 ; v3(104.95,26.3) C29.2@105.875,26.3 ; v3(104.95,27.9) R7.2@105.875,27.9 ; v3(105.9,5.5) C40.2@106.875,5.5 ; v3(105.9,8) R17.2@106.875,8 ; R18.2@118.5,7.225 v3(118.5,8.15) ; v3(129.09,16.505) 130.015,16.505 v3(130.015,15.581)
  Top Layer w0.6: v1(38.4,47.9) C65.2@39.275,47.9 ; C73.1@104.3,65.526 v1(104.3,66.5) ; C74.2@106.4,65.526 v1(106.4,66.5) ; v1(113,54.226) R83.2@113,55.1
  Top Layer w0.7: C71.2@101.5,45.274 101.525,45.3 v1(102.3,45.3) C76.2@103.1,45.3
  Signal Layer 2 w0.381: X1.B12@135.67,17.8 X1.B12@135.67,18.6 ; X1.B1@135.67,22.6 X1.B1@135.67,23.4
  Bottom Layer w0.203: D17.3@22.6,48.875 22.6,49.531
  Bottom Layer w0.254: v1(90.9,50.4) 91.1,50.6 C70.2@92.074,50.6 ; v1(90.9,55) 91.974,55 C75.2@92.074,55.1 ; v1(90.9,57.1) C69.2@92.074,57.1
  Bottom Layer w0.3: C72.2@107.1,45.3 v1(108.1,45.3)
  Bottom Layer w0.45: C51.2@117.9,29.704 v3(117.9,30.478) ; C47.2@121.426,20.48 v2(122.2,20.48)
  Bottom Layer w0.508: v3(84.25,22.2) C98.2@86.775,22.2 ; v3@99.5,15.5 C103.2@100.5,15.5 ; v3(104.95,21.2) C49.2@105.875,21.2 ; v3(104.95,23.3) C48.2@105.875,23.3 ; v3(114.5,12.502) C50.2@114.5,13.277 ; v3(116,12.502) C46.2@116,13.277
  Bottom Layer w0.6: C68.2@97.674,61.5 97.7,61.475 v1(97.7,60.6) ; v1(103.174,60.625) C67.2@103.174,61.5
  other v1: 131.5,4.5 132.2,4.5 62.1,5.6 45,6 55,6 95,6 125,6 72.3,10 73.8,10 75.3,10 78.4,10.6 50,11 100,11 78.4,11.3 72.3,11.5 73.8,11.5 75.3,11.5 72.3,13 75.3,13 58.1,13.3 58.1,14 72.3,14.5 73.8,14.5 75.3,14.5 67.1,15.4 45.8,15.7 55,16 65,16 73.8,16 75.3,16 125,16 46.7,16.9 57.8,17.2 80,21 69,22.3 69,24.1 75,26 46.7,26.9 45.8,28.1 52.6,29.5 54.1,29.5 80,31 100,31 120,31 130,31 68.5,31.5 68.5,32.2 68.5,32.9 59.9,33.333 137.6,34.2 137.6,34.9 56.85,35.6 65,36 75,36 85,36 135,36 137.6,37 137.6,37.7 137.6,40.4 50,41 60,41 70,41 120,41 130,41 137.6,41.1 75,46 30.5,46.5 30.5,47.2 34.821,47.9 34.821,49.297 34,50.3 6.1,53.6 6.8,53.6 8.8,53.6 9.5,53.6 11.4,53.6 12.1,53.6 20,54 5,59 15,59 25,59 37.456,59.405 38.646,60.475 32.7,61.5 33.6,62.3 35.2,63.8 10,64 20,64 30,64 40,64 50,64 60,64 70,64 112.95,66.42 121,67 121.7,67 124,67 124.7,67 127.4,67.1 128.1,67.1 118.4,68 119.1,68 107.9,68.2 15,69 25,69 35,69 45,69 55,69 65,69 95,69 115,69 109.425,69.274 18.4,70.6 19.1,70.6
  other v2: 111.164,18.884 112.057,18.884 112.95,18.884 113.844,18.884 114.737,18.884 115.63,18.884 111.164,19.777 112.057,19.777 112.95,19.777 113.844,19.777 114.737,19.777 115.63,19.777 111.164,20.67 112.057,20.67 112.95,20.67 113.844,20.67 114.737,20.67 115.63,20.67 111.164,21.564 112.057,21.564 112.95,21.564 113.844,21.564 114.737,21.564 115.63,21.564 111.164,22.457 112.057,22.457 112.95,22.457 113.844,22.457 114.737,22.457 115.63,22.457 111.164,23.35 112.057,23.35 112.95,23.35 113.844,23.35 114.737,23.35 115.63,23.35 40.757,52.177 41.65,52.177 42.544,52.177 43.437,52.177 40.757,53.07 41.65,53.07 42.544,53.07 43.437,53.07 99.964,53.284 100.857,53.284 101.75,53.284 102.644,53.284 103.537,53.284 104.43,53.284 40.757,53.964 41.65,53.964 42.544,53.964 43.437,53.964 99.964,54.177 100.857,54.177 101.75,54.177 102.644,54.177 103.537,54.177 104.43,54.177 40.757,54.857 41.65,54.857 42.544,54.857 43.437,54.857 99.964,55.07 100.857,55.07 101.75,55.07 102.644,55.07 103.537,55.07 104.43,55.07 99.964,55.964 100.857,55.964 101.75,55.964 102.644,55.964 103.537,55.964 104.43,55.964 99.964,56.857 100.857,56.857 101.75,56.857 102.644,56.857 103.537,56.857 104.43,56.857 99.964,57.75 100.857,57.75 101.75,57.75 102.644,57.75 103.537,57.75 104.43,57.75
  other v3: 99.5,15.1 99.5,15.8 112.9,32.247 114.3,32.247 116.575,32.247 117.803,32.247 118.942,32.247 112.9,35.35 112.9,36.35 114.4,36.35 115.9,36.35 117.4,36.35 118.9,36.35
  other v6: 41,34.2 44.7,34.2 48.4,34.2
GPIO0: D27.1 IC13.66 | length 8.4
  Top Layer w0.178: IC13.66@107.45,49.45 107.958,49.45 108.2,49.208 108.2,48.131 108.47,47.861 113.089,47.861 D27.1@114.1,46.85
GPIO1: IC13.64 R89.2 | length 4.5
  Top Layer w0.147: IC13.64@106.45,49.45 106.45,48.855 106.3,48.705 106.3,46.1 R89.2@107.1,45.3
GPIO2: D28.1 IC13.63 | length 8.8
  Top Layer w0.147: IC13.63@105.95,49.45 105.95,45.012 106.463,44.5 108.85,44.5 D28.1@109.7,45.35
GPIO3: IC13.47 X7.P9 | length 40.3
  Top Layer w0.152: v1(96.6,48.1) 97.155,48.1 97.95,48.895 IC13.47@97.95,49.45
  Signal Layer 3 w0.203: v1(96.6,48.1) 98.7,46 119.1,46 119.5,46.4 119.5,57.885 X7.P9@121.38,59.765
GPIO4: IC13.27 | length 1
  Top Layer w0.147: v1(95.218,58.445) 95.54,58.766 IC13.27@96.134,58.766
GPIO5: IC13.26 R91.2 | length 40.5
  Top Layer w0.152: v1(94.4,58.5) 94.4,58.95 94.7,59.25 IC13.26@96.15,59.25
  Signal Layer 3 w0.203: v1(94.4,58.5) 93.3,57.4 93.3,49.435 93.935,48.8 96.9,48.8 99.3,46.4 117.1,46.4 117.5,46.8 117.5,48.3 v1(117,48.8)
  Bottom Layer w0.3: v1(117,48.8) R91.2@117.874,48.8
GPIO6: IC13.14
GPIO7: IC13.13
I2C2_SCL: IC12.6 IC13.61 R85.2 X4.6 | length 44.1
  Top Layer w0.152: R85.2@98.326,39.8 98.491,39.635 IC12.6@100.76,39.635 103.035,39.635 103.381,39.981 103.381,42.392 105.102,44.113 105.102,48.62 104.95,48.772 IC13.61@104.95,49.45
  Signal Layer 3 w0.203: v1(102.2,39.635) 128.905,39.635 X4.6@130.27,38.27
I2C2_SDA: IC12.5 IC13.60 R86.2 X4.8 | length 45.5
  Top Layer w0.152: IC12.5@101,40.905 102.645,40.905 103,41.26 103,42.55 104.721,44.271 104.721,48.374 104.45,48.645 IC13.60@104.45,49.45
  Top Layer w0.178: R86.2@98.326,41.3 98.526,41.1 100.565,41.1 IC12.5@100.76,40.905
  Signal Layer 3 w0.203: v1(102.2,40.9) 103.483,40.9 104.283,40.1 130.98,40.1 X4.8@132.81,38.27
I\N\T\: D8.2 IC9.25 R70.2 X6.3 | length 13.7
  Top Layer w0.254: R70.2@37.426,44.1 38.126,43.4 X6.3@40.06,43.4 41.85,45.19 IC9.25@41.85,50.55
  Bottom Layer w0.381: X6.3@40.06,43.4 40.06,41.429 D8.2@40.689,40.8
IRQ: IC13.62 TP6.1 | length 6.8
  Top Layer w0.152: IC13.62@105.483,49.417 105.483,44.917 TP6.1@107.1,43.3
LED2: IC1.24
LED3: IC1.33 | length 6.8
  Top Layer w0.203: IC1.33@116.8,22.35 123.295,22.35 v2(123.525,22.58)
LINK_ST: IC9.4 R60.1 TP4.1 | length 6.5
  Top Layer w0.254: IC9.4@42.85,56.45 42.85,57.776 44.375,59.3 v1(44.9,59.3) TP4.1@44.9,60.6 TP4.1@44.9,60.8
  Bottom Layer w0.381: v1(44.9,59.3) R60.1@45.875,59.3
MDC: D7.2 IC9.27 X6.1 | length 12.7
  Top Layer w0.254: IC9.27@42.85,50.55 42.85,45.69 X6.1@45.14,43.4
  Bottom Layer w0.381: X6.1@45.14,43.56 D7.2@48.393,40.307
MDIO: D9.2 IC9.26 R71.2 X6.2 | length 17
  Top Layer w0.254: R71.2@37.426,42.6 38.126,41.9 41.1,41.9 X6.2@42.6,43.4 ; X6.2@42.35,43.3 IC9.26@42.35,50.55
  Bottom Layer w0.381: X6.2@42.6,43.4 42.6,41.614 43.314,40.9 D9.2@44.136,40.9
NetC1_1: C1.1 D1.2 D6.2 IC4.3 R9.1 T2.mb | length 3
  Top Layer w0.457: 53.647,22.272 54,22.625 ; 53.647,22.978 54,22.625 ; IC4.3@55.984,22.625 54,22.625
NetC2_1: C2.1 R3.2 | length 1.8
  Top Layer w0.762: C2.1@44,21.1 R3.2@44,22.9
NetC2_2: C2.2 D6.1 FB12.2 IC4.2 T5.3 T7.mb | length 27.7
  Top Layer w0.381: v1(54.5,23.7) 54.925,23.275 IC4.2@55.984,23.275
  Top Layer w1.016: FB12.2@45.8,18.8 C2.2@45.8,21.1 48.1,21.1 v1(48.5,20.7) ; 49.485,18.35 49.485,18.056 ; T5.3@49.6,13.1 49.485,13.215 49.5,15.6 ; T7.mb@50.67,16.871 49.485,18.056 ; T7.mb@50.685,16.785 49.5,15.6 ; v1(48.5,20.7) 49.4,19.8 49.485,19.8 ; v1(48.5,20.7) D6.1@49.485,20.7 49.485,19.8 ; 49.485,18.056 49.5,15.6 ; 49.485,18.056 49.485,19.8
  Bottom Layer w0.381: v1(48.5,20.7) 51.5,23.7 v1(54.5,23.7)
NetC7_1: C7.1 L2.3 | length 1.3
  Top Layer w0.206: C7.1@126.7,19 126.93,18.77 127.372,18.77 127.547,18.945 L2.3@127.875,18.945
NetC8_1: C8.1 L2.2 | length 1.4
  Top Layer w0.206: C8.1@126.7,17.97 127.1,18.37 127.372,18.37 127.547,18.195 L2.2@127.875,18.195
NetC9_1: C9.1 FB3.1 IC1.25 | length 8
  Top Layer w0.254: C9.1@119.374,16.855 118.725,16.855 117.419,18.161 116.989,18.161 IC1.25@116.8,18.35 117.536,18.35 118.806,17.08 C9.1@119.5,17.08
  Top Layer w0.508: FB3.1@119.675,15.305 C9.1@119.675,16.905
NetC26_1: C26.1 C105.1 IC2.4 IC2.5 L11.2
NetC29_1: C29.1 IC1.48 | length 4
  Top Layer w0.2: C29.1@107.426,26.305 108.37,26.305 110.175,24.5 IC1.48@110.65,24.5
NetC30_2: C30.2 IC1.40 Y1.1 | length 13.9
  Top Layer w0.203: IC1.40@114.65,24.5 114.65,26.154 115.4,26.904 115.4,31.63 115.9,32.13 115.9,34.105 Y1.1@116.8,35.005 ; 115.4,31.605 115.9,32.105 ; Y1.1@116.9,35.08 C30.2@118.7,35.08
NetC31_2: C31.2 IC1.41 Y1.3 | length 10.7
  Top Layer w0.203: C31.2@113.2,33.28 Y1.3@114.725,33.28 ; IC1.41@114.15,24.5 114.15,25.255 114.3,25.405 114.3,26.37 115,27.07 Y1.3@115,33.305
NetC32_1: C32.1 R9.2 | length 2.3
  Top Layer w0.762: R9.2@56.1,29.129 56.3,29.329 56.3,30.2 C32.1@57.1,31
NetC33_1: C33.1 C38.1 T1.6 | length 4.6
  Top Layer w0.381: C38.1@21.074,35.3 C33.1@21.074,36.8 ; C33.1@21.074,36.909 21.565,37.4 T1.6@21.565,39.82
NetC33_2: C33.2 C38.2 C41.1 T1.7 | length 11.3
  Top Layer w0.381: C41.1@17.47,41.47 22.435,41.47 22.835,41.07 T1.7@22.835,39.82 C38.2@22.835,35.3
NetC34_1: C34.1 R10.2 | length 2.5
  Top Layer w0.381: C34.1@60,30.6 R10.2@61.726,32.326 ; R10.2@61.626,32.326 R10.2@61.7,32.326
NetC35_1: C35.1 R13.2
NetC36_1: C36.1 IC4.4 IC4.10 | length 17.9
  Top Layer w0.254: IC4.4@55.984,21.975 55.075,21.975 54.8,21.7 v1(54.8,18.7) 55.8,18.7 C36.1@56,18.5 ; IC4.10@60.416,22.625 61.925,22.625 v1(62.05,22.5)
  Bottom Layer w0.254: v1(54.8,18.7) 58.125,18.7 58.4,18.975 58.4,22.046 58.854,22.5 v1(62.05,22.5)
NetC37_1: C37.1 T1.2 T1.3 | length 7.4
  Top Layer w0.381: T1.3@21.57,48.34 22.84,48.34 22.84,47.155 23.105,46.89 C37.1@27.7,46.89
NetC41_2: C41.2 R27.1 | length 2
  Top Layer w0.508: C41.2@14.3,41.5 R27.1@14.3,43.5
NetC45_1: C45.1 C52.1 C126.1 R77.2 R78.2 R79.2 R80.2 R81.2 R164.2 | length 24.4
  Top Layer w0.762: C126.1@114.2,62.3 114.997,62.3 ; 115.461,61.836 114.997,62.3 ; R164.2@115.625,60.7 C45.1@115.625,62 ; 115.7,61.9 C45.1@116,62.2 ; v1(119.2,62.3) v1(118.5,62.3) 117.6,62.3 114.997,62.3
  Bottom Layer w0.254: R80.2@122.974,50 R79.2@122.974,51.6 123.8,52.425 123.8,53.874 R81.2@122.974,54.7
  Bottom Layer w0.381: R81.2@122.974,54.7 R78.2@122.974,56.2 R77.2@122.974,58.7
  Bottom Layer w0.508: v1(118.5,62.3) v1(119.2,62.3) 122.283,62.3 122.974,61.609 R77.2@122.974,58.7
